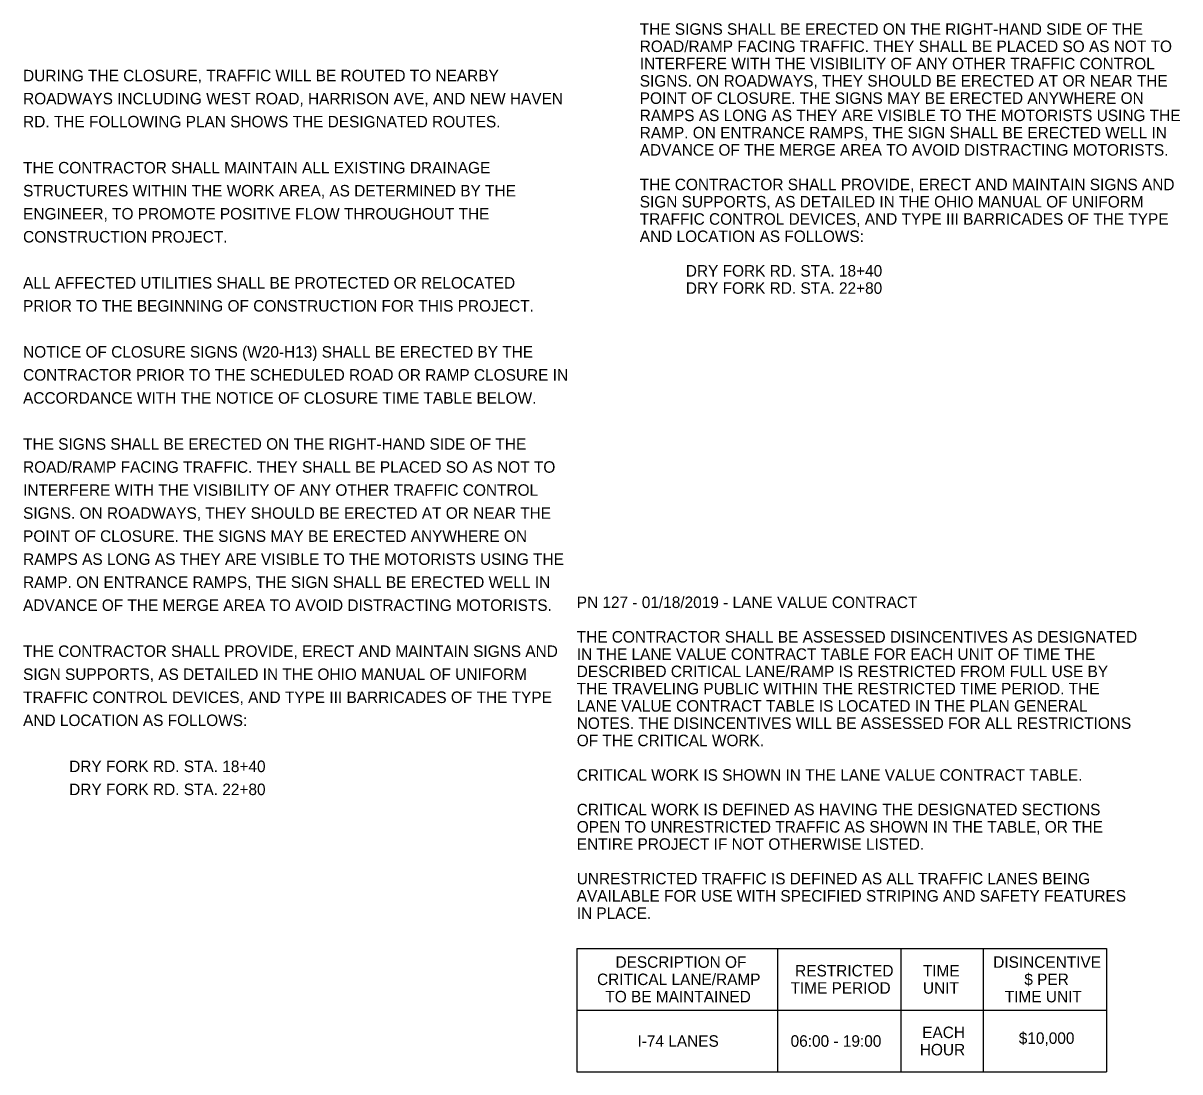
# Model space of a CAD drawing. Extents: x -65.5 to 34, y -24.3 to 23.1.
# Drawn here: x -65.5 to -51.44, y -13.71 to -0.96 of the extents above; entities that cross this region are included whole.
import ezdxf

# ---------------------------------------------------------------- set-up
doc = ezdxf.new("R2010")
doc.units = 0
doc.layers.add('SH_Text', color=7, linetype='Continuous')

msp = doc.modelspace()

# ---------------------------------------------------------------- linework, layer by layer
at = {"layer": 'SH_Text'}
for p, q in [((-58.769, -12.211), (-58.769, -12.961)), ((-56.329, -12.211), (-56.329, -12.961)), ((-54.829, -12.211), (-54.829, -12.961)), ((-53.829, -12.211), (-53.829, -12.961)), ((-52.329, -12.211), (-52.329, -12.961)), ((-58.769, -12.961), (-58.769, -13.711)), ((-56.329, -12.961), (-56.329, -13.711)), ((-54.829, -12.961), (-54.829, -13.711)), ((-53.829, -12.961), (-53.829, -13.711)), ((-52.329, -12.961), (-52.329, -13.711))]:
    msp.add_line(p, q, dxfattribs=at)
for points in [[(-58.769, -12.211), (-56.329, -12.211), (-54.829, -12.211), (-53.829, -12.211), (-52.329, -12.211)], [(-58.769, -12.961), (-56.329, -12.961), (-54.829, -12.961), (-53.829, -12.961), (-52.329, -12.961)], [(-58.769, -13.711), (-56.329, -13.711), (-54.829, -13.711), (-53.829, -13.711), (-52.329, -13.711)]]:
    msp.add_lwpolyline(points, dxfattribs=at)

# ---------------------------------------------------------------- texts
for s, p in [('THE SIGNS SHALL BE ERECTED ON THE RIGHT-HAND SIDE OF THE ', (-58.003, -1.1)), ('ROAD/RAMP FACING TRAFFIC. THEY SHALL BE PLACED SO AS NOT TO ', (-58.003, -1.31)), ('INTERFERE WITH THE VISIBILITY OF ANY OTHER TRAFFIC CONTROL ', (-58.003, -1.52)), ('DURING THE CLOSURE, TRAFFIC WILL BE ROUTED TO NEARBY ', (-65.5, -1.666)), ('SIGNS. ON ROADWAYS, THEY SHOULD BE ERECTED AT OR NEAR THE ', (-58.003, -1.73)), ('ROADWAYS INCLUDING WEST ROAD, HARRISON AVE, AND NEW HAVEN ', (-65.5, -1.946)), ('POINT OF CLOSURE. THE SIGNS MAY BE ERECTED ANYWHERE ON ', (-58.003, -1.94)), ('RD. THE FOLLOWING PLAN SHOWS THE DESIGNATED ROUTES. ', (-65.5, -2.226)), ('RAMPS AS LONG AS THEY ARE VISIBLE TO THE MOTORISTS USING THE ', (-58.003, -2.15)), ('RAMP. ON ENTRANCE RAMPS, THE SIGN SHALL BE ERECTED WELL IN ', (-58.003, -2.36)), ('ADVANCE OF THE MERGE AREA TO AVOID DISTRACTING MOTORISTS.', (-58.003, -2.57)), ('THE CONTRACTOR SHALL MAINTAIN ALL EXISTING DRAINAGE ', (-65.5, -2.786)), ('STRUCTURES WITHIN THE WORK AREA, AS DETERMINED BY THE ', (-65.5, -3.066)), ('THE CONTRACTOR SHALL PROVIDE, ERECT AND MAINTAIN SIGNS AND ', (-58.003, -2.99)), ('SIGN SUPPORTS, AS DETAILED IN THE OHIO MANUAL OF UNIFORM ', (-58.003, -3.2)), ('ENGINEER, TO PROMOTE POSITIVE FLOW THROUGHOUT THE ', (-65.5, -3.346)), ('TRAFFIC CONTROL DEVICES, AND TYPE III BARRICADES OF THE TYPE ', (-58.003, -3.41)), ('CONSTRUCTION PROJECT.', (-65.5, -3.626)), ('AND LOCATION AS FOLLOWS:', (-58.003, -3.62)), ('DRY FORK RD. STA. 18+40', (-57.443, -4.04)), ('ALL AFFECTED UTILITIES SHALL BE PROTECTED OR RELOCATED ', (-65.5, -4.186)), ('DRY FORK RD. STA. 22+80', (-57.443, -4.25)), ('PRIOR TO THE BEGINNING OF CONSTRUCTION FOR THIS PROJECT.', (-65.5, -4.466)), ('NOTICE OF CLOSURE SIGNS (W20-H13) SHALL BE ERECTED BY THE ', (-65.5, -5.026)), ('CONTRACTOR PRIOR TO THE SCHEDULED ROAD OR RAMP CLOSURE IN ', (-65.5, -5.306)), ('ACCORDANCE WITH THE NOTICE OF CLOSURE TIME TABLE BELOW.', (-65.5, -5.586)), ('THE SIGNS SHALL BE ERECTED ON THE RIGHT-HAND SIDE OF THE ', (-65.5, -6.146)), ('ROAD/RAMP FACING TRAFFIC. THEY SHALL BE PLACED SO AS NOT TO ', (-65.5, -6.426)), ('INTERFERE WITH THE VISIBILITY OF ANY OTHER TRAFFIC CONTROL ', (-65.5, -6.706)), ('SIGNS. ON ROADWAYS, THEY SHOULD BE ERECTED AT OR NEAR THE ', (-65.5, -6.986)), ('POINT OF CLOSURE. THE SIGNS MAY BE ERECTED ANYWHERE ON ', (-65.5, -7.266)), ('RAMPS AS LONG AS THEY ARE VISIBLE TO THE MOTORISTS USING THE ', (-65.5, -7.546)), ('RAMP. ON ENTRANCE RAMPS, THE SIGN SHALL BE ERECTED WELL IN ', (-65.5, -7.826)), ('ADVANCE OF THE MERGE AREA TO AVOID DISTRACTING MOTORISTS.', (-65.5, -8.106)), ('PN 127 - 01/18/2019 - LANE VALUE CONTRACT', (-58.769, -8.071)), ('THE CONTRACTOR SHALL BE ASSESSED DISINCENTIVES AS DESIGNATED ', (-58.769, -8.491)), ('THE CONTRACTOR SHALL PROVIDE, ERECT AND MAINTAIN SIGNS AND ', (-65.5, -8.666)), ('IN THE LANE VALUE CONTRACT TABLE FOR EACH UNIT OF TIME THE ', (-58.769, -8.701)), ('SIGN SUPPORTS, AS DETAILED IN THE OHIO MANUAL OF UNIFORM ', (-65.5, -8.946)), ('DESCRIBED CRITICAL LANE/RAMP IS RESTRICTED FROM FULL USE BY ', (-58.769, -8.911)), ('THE TRAVELING PUBLIC WITHIN THE RESTRICTED TIME PERIOD. THE ', (-58.769, -9.121)), ('TRAFFIC CONTROL DEVICES, AND TYPE III BARRICADES OF THE TYPE ', (-65.5, -9.226)), ('LANE VALUE CONTRACT TABLE IS LOCATED IN THE PLAN GENERAL ', (-58.769, -9.331)), ('AND LOCATION AS FOLLOWS:', (-65.5, -9.506)), ('NOTES. THE DISINCENTIVES WILL BE ASSESSED FOR ALL RESTRICTIONS ', (-58.769, -9.541)), ('OF THE CRITICAL WORK.', (-58.769, -9.751)), ('DRY FORK RD. STA. 18+40', (-64.94, -10.066)), ('CRITICAL WORK IS SHOWN IN THE LANE VALUE CONTRACT TABLE.', (-58.769, -10.171)), ('DRY FORK RD. STA. 22+80', (-64.94, -10.346)), ('CRITICAL WORK IS DEFINED AS HAVING THE DESIGNATED SECTIONS ', (-58.769, -10.591)), ('OPEN TO UNRESTRICTED TRAFFIC AS SHOWN IN THE TABLE, OR THE ', (-58.769, -10.801)), ('ENTIRE PROJECT IF NOT OTHERWISE LISTED.', (-58.769, -11.011)), ('UNRESTRICTED TRAFFIC IS DEFINED AS ALL TRAFFIC LANES BEING ', (-58.769, -11.431)), ('AVAILABLE FOR USE WITH SPECIFIED STRIPING AND SAFETY FEATURES ', (-58.769, -11.641)), ('IN PLACE.', (-58.769, -11.851)), ('DESCRIPTION OF ', (-58.298, -12.446)), ('DISINCENTIVE ', (-53.706, -12.446)), ('CRITICAL LANE/RAMP ', (-58.522, -12.656)), ('RESTRICTED ', (-56.114, -12.551)), ('TIME ', (-54.561, -12.551)), ('$ PER ', (-53.328, -12.656)), ('TIME PERIOD', (-56.17, -12.761)), ('UNIT', (-54.56, -12.761)), ('TO BE MAINTAINED', (-58.421, -12.866)), ('TIME UNIT', (-53.565, -12.866)), ('EACH', (-54.569, -13.301)), ('I-74 LANES', (-58.031, -13.406)), ('06:00 - 19:00', (-56.169, -13.406)), ('$10,000', (-53.395, -13.371)), ('HOUR', (-54.598, -13.511))]:
    msp.add_text(s, height=0.14, dxfattribs=at).set_placement(p)

doc.saveas('drawing.dxf')
